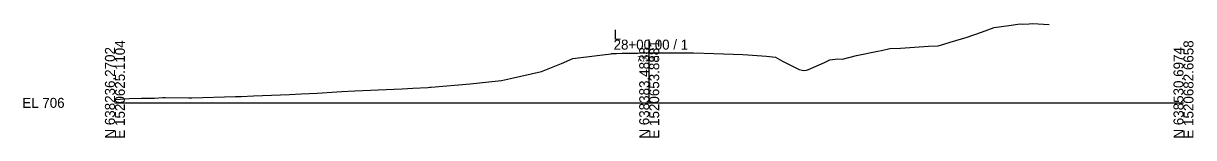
# Model space of a CAD drawing. Extents: x -26 to 3903, y -10 to 9531.
# Drawn here: x 974.3 to 1302.8, y 7990.3 to 8022.2 of the extents above; entities that cross this region are included whole.
import ezdxf

# ---------------------------------------------------------------- set-up
doc = ezdxf.new("R2010")
doc.units = 0
for name, color, linetype in [('Default', 7, 'Continuous'), ('Exist Cross Section Cell', 7, 'Continuous'), ('Exist XS Center Line Elevation Label', 7, 'Continuous'), ('Exist XS Ground Line', 7, 'Continuous')]:
    doc.layers.add(name, color=color, linetype=linetype)

msp = doc.modelspace()

# ---------------------------------------------------------------- linework, layer by layer
at = {"layer": 'Exist Cross Section Cell'}
for p, q in [((1150, 8000), (1150, 8017.68)), ((1000, 8000), (1150, 8000)), ((1150, 8000), (1300, 8000))]:
    msp.add_line(p, q, dxfattribs=at)
at = {"layer": 'Exist XS Ground Line'}
msp.add_lwpolyline([(1000, 8000.89), (1000.21, 8000.91), (1004.01, 8001.18), (1007.45, 8001.29), (1011.15, 8001.33), (1013.42, 8001.5), (1014.07, 8001.46), (1020.79, 8001.41), (1021.6, 8001.43), (1033.87, 8001.74), (1035.47, 8001.77), (1038.88, 8001.93), (1049.06, 8002.36), (1052.28, 8002.52), (1056.79, 8002.75), (1062.3, 8003.1), (1063.69, 8003.15), (1067.37, 8003.39), (1078.34, 8003.82), (1080.66, 8003.95), (1083.68, 8004.1), (1087.88, 8004.33), (1088.44, 8004.36), (1088.5, 8004.37), (1088.78, 8004.39), (1099.71, 8005.29), (1107.64, 8006.2), (1108.57, 8006.26), (1111.06, 8006.81), (1119.78, 8008.77), (1125.35, 8011.02), (1128.58, 8012.37), (1135.39, 8013.25), (1139.33, 8013.75), (1139.53, 8013.76), (1139.89, 8013.78), (1140.16, 8013.8), (1140.79, 8013.82), (1142.37, 8013.87), (1143.65, 8013.89), (1144.91, 8013.91), (1146.81, 8013.94), (1147.45, 8013.95), (1148.69, 8013.96), (1149.64, 8013.97), (1150.23, 8013.98), (1150.63, 8013.97), (1152.33, 8013.98), (1153.3, 8013.99), (1153.53, 8014), (1155.86, 8014.01), (1157.4, 8014.02), (1158.39, 8014.02), (1159.87, 8014.02), (1160.94, 8014.02), (1161.38, 8014.02), (1162.44, 8014.01), (1168.17, 8013.79), (1176.27, 8013.49), (1177.73, 8013.4), (1182.89, 8013.04), (1185.45, 8012.78), (1187.39, 8011.64), (1192.14, 8009.33), (1192.97, 8009.14), (1193.38, 8009.05), (1194.19, 8009.17), (1194.71, 8009.3), (1199.17, 8011.25), (1200.68, 8012.05), (1202.93, 8012.29), (1204.29, 8012.26), (1208.2, 8013.21), (1214.19, 8014.44), (1215.25, 8014.67), (1217.56, 8015.2), (1220.59, 8015.31), (1228.41, 8015.82), (1231.09, 8015.99), (1232.68, 8016.42), (1234.45, 8016.95), (1239.26, 8018.35), (1243.26, 8019.79), (1246.82, 8021.06), (1251, 8021.62), (1254.11, 8022.07), (1254.94, 8022.05), (1256.63, 8022.11), (1257.64, 8022.19), (1262.31, 8021.89)], dxfattribs=at)

# ---------------------------------------------------------------- texts
at = {"layer": 'Default'}
msp.add_text('-', height=0.0001, dxfattribs=at).set_placement((1000, 8000))
at = {"layer": 'Exist Cross Section Cell'}
for s, p in [('L', (1140, 8017.68)), ('28+00.00 / 1', (1140, 8014.88)), ('EL 706', (974, 7998.6))]:
    msp.add_text(s, height=2.8, dxfattribs=at).set_placement(p)
for s, p in [('E 1520625.1104', (1002.8, 7990)), ('E 1520653.8881', (1152.8, 7990)), ('E 1520682.6658', (1302.8, 7990)), ('N 638236.2702', (1000, 7990)), ('N 638383.4838', (1150, 7990)), ('N 638530.6974', (1300, 7990))]:
    msp.add_text(s, height=2.8, rotation=90, dxfattribs=at).set_placement(p)
at = {"layer": 'Exist XS Center Line Elevation Label'}
msp.add_text('719.97', height=1.5, rotation=0.8401, dxfattribs=at).set_placement((1146.55, 8011.55))

doc.saveas('drawing.dxf')
